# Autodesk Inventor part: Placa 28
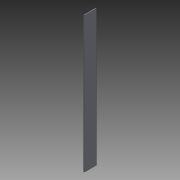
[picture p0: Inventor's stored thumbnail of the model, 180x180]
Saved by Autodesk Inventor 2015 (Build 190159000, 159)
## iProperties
Created: 2015-04
Part Number: Placa 28
Material: Generic
Document SubType Name: Modeling
Designer: suporte
Density: 1 g/cm^3
Appearance: Default
Author: suporte
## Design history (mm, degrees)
sketch "Sketch1"
  geometry: L1 (-875, 460)-(-875, 495) reference; L2 (-825, 295)-(-875, 295) reference; L3 (-875, 295)-(-887.5, 295); L4 (-887.5, 295)-(-887.5, 480); L5 (-887.5, 480)-(-875, 480); L6 (-875, 480)-(-875, 295); 1 further point
  constraints: 8 end point, 2 parallel, 1 horizontal, 1 perpendicular
  dimensions: "d0" = 12.5 distance of L4.end L5.end; "d1" = 185 distance of L3.end L4.end
extrude "Extrusion1" new body sketch "Sketch1" distance "d2" = 2100; taper "d3" = 0 deg
body "Solid1"
node "Reference1"
node "Reference2"
